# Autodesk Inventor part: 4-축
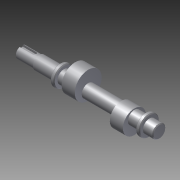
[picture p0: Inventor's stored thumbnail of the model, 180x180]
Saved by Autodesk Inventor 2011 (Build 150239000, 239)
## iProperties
Created: 2014-12
Part Number: 4-축
Document SubType Name: Modeling
Designer: user
Density: 1 g/cm^3
Author: user
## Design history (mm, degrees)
sketch "스케치1"
  geometry: L1 (90, 0)-(-90, 0); L2 (90, 0)-(90, 7.5); L3 (90, 7.5)-(66, 7.5); L4 (66, 7.5)-(66, 8.5); L5 (66, 8.5)-(39, 8.5); L6 (39, 8.5)-(39, 13); L7 (39, 13)-(34, 13); L8 (34, 13)-(34, 8.5); L9 (34, 8.5)-(-72, 8.5); L10 (-72, 8.5)-(-72, 13); L11 (-72, 13)-(-77, 13); L12 (-77, 13)-(-77, 8.5); L13 (-77, 8.5)-(-90, 8.5); L14 (-90, 8.5)-(-90, 0); 2 further points
  constraints: 28 end point, 5 parallel, 3 horizontal, 3 vertical, 2 perpendicular, 1 coincident, 1 collinear, 1 midpoint
  dimensions: "d0" = 180 distance of L1.start L1.end; "d1" = 15 diameter of L3 L1; "d2" = 17 diameter of L5 L1; "d3" = 26 diameter of L7 L1; "d4" = 17 diameter of L13 L1; "d5" = 26 diameter of L11 L1; "d6" = 17 diameter of L9 L1; "d7" = 13 distance of L12.end L13.end; "d8" = 5 distance of L10.end L11.end; "d9" = 24 distance of L2.end L3.end; "d10" = 27 distance of L4.end L5.end; "d11" = 5 distance of L6.end L7.end
revolve "회전1" sketch "스케치1" stored, may be unused: angle "d12" = 90 deg
chamfer "모따기1" distance "d13" = 1; stored, may be unused: second distance "d14" = 2, angle "d15" = 45 deg
node "작업 평면1"
sketch "스케치2"
  geometry: C1 r 8.5 at (0, 0) reference; C2 r 15 at (5, 0); 1 further point
  constraints: 1 centre point, 1 horizontal alignment
  dimensions: "d17" = 30 diameter of C2; "d18" = 5 distance of C1.centre C2.centre
extrude "돌출1" join sketch "스케치2" distance "d19" = 17; taper "d20" = 0 deg
node "작업 평면2"
sketch "스케치3"
  geometry: C1 r 8.5 at (0, 5) reference; C2 r 17.5 at (0, 11); 1 further point
  constraints: 1 centre point, 1 vertical alignment
  dimensions: "d22" = 6 distance of C1.centre C2.centre; "d23" = 35 diameter of C2
extrude "돌출2" join sketch "스케치3" distance "d24" = 17; taper "d25" = 0 deg
node "작업 평면3"
sketch "스케치4" dims "d26" = 5
  geometry: L1 (12, 0)-(-11, 0) reference; L2 (12, 0)-(12, 4) reference; L3 (12, -4)-(12, 0) reference; L4 (39, -4)-(12, -4) reference; L5 (39, -9.367)-(39, -4) reference; L6 (43, -10.618)-(40, -10.618) reference; L7 (44, -4)-(44, -9.367) reference; L8 (58.5, -4)-(44, -4) reference; L9 (58.5, -17.436)-(58.5, -4) reference; L10 (75.5, -17.436)-(58.5, -17.436) reference; L11 (75.5, -4)-(75.5, -17.436) reference; L12 (118.5, -4)-(75.5, -4) reference; L13 (118.5, -8.292)-(118.5, -4) reference; L14 (135.5, -8.292)-(118.5, -8.292) reference; L15 (135.5, -4)-(135.5, -8.292) reference; L16 (150, -4)-(135.5, -4) reference; L17 (150, -9.367)-(150, -4) reference; L18 (154, -10.618)-(151, -10.618) reference; L19 (155, -4)-(155, -9.367) reference; L20 (167, -4)-(155, -4) reference; L21 (155, 4)-(167, 4) reference; L22 (155, 9.367)-(155, 4) reference; L23 (151, 10.618)-(154, 10.618) reference; L24 (150, 4)-(150, 9.367) reference; L25 (135.5, 4)-(150, 4) reference; L26 (135.5, 8.292)-(135.5, 4) reference; L27 (118.5, 8.292)-(135.5, 8.292) reference; L28 (118.5, 4)-(118.5, 8.292) reference; L29 (75.5, 4)-(118.5, 4) reference; L30 (75.5, 17.436)-(75.5, 4) reference; L31 (58.5, 17.436)-(75.5, 17.436) reference; L32 (58.5, 4)-(58.5, 17.436) reference; L33 (44, 4)-(58.5, 4) reference; L34 (44, 9.367)-(44, 4) reference; L35 (40, 10.618)-(43, 10.618) reference; L36 (39, 4)-(39, 9.367) reference; L37 (12, 4)-(39, 4) reference; L38 (5.5, 2.5)-(-17.175, 2.5); L39 (-17.175, 2.5)-(-17.175, -2.5); L40 (-17.175, -2.5)-(5.5, -2.5); L41 (5.5, -2.5)-(5.5, 2.5); L42 (-12, -6.5)-(-12, 6.5) reference; 4 further points
  constraints: 8 end point, 2 parallel, 1 horizontal, 1 horizontal alignment, 1 midpoint, 1 perpendicular, 1 vertical alignment, 12 other
  dimensions: "d27" = 20 dimension on L42
extrude "돌출3" cut sketch "스케치4" distance "d28" = 3; taper "d29" = 0 deg
node "솔리드1"
node "절단 모서리 투영1"
node "절단 모서리 투영2"
node "절단 모서리 투영3"
other parameters: "d16" = -32.5, "d21" = 43
